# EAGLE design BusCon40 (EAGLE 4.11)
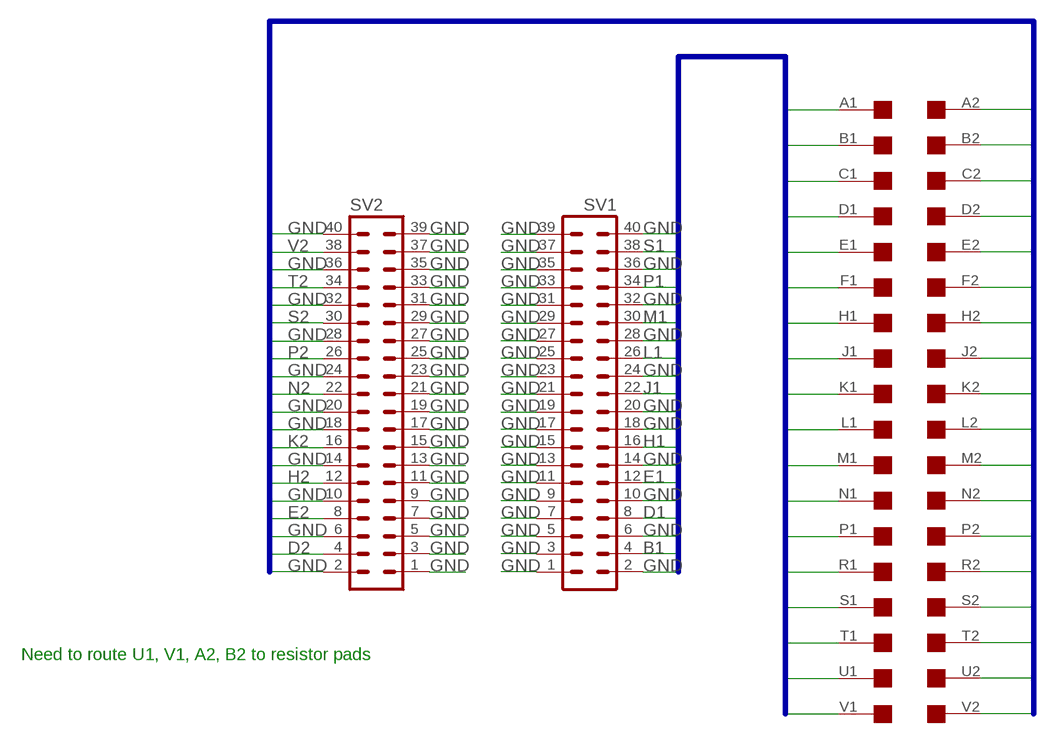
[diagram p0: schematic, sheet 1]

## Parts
SV1  MA20-2W  [MA20-2W]
SV2  MA20-2W  [MA20-2W]
U$1  DEC-FLIPCHIP  [DEC-FLIPCHIP]

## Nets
A2: U$1.A2
B1: SV1.4 U$1.B1
B2: U$1.B2
D1: SV1.8 U$1.D1
D2: SV2.4 U$1.D2
E1: SV1.12 U$1.E1
E2: SV2.8 U$1.E2
GND: SV1.1 SV1.2 SV1.3 SV1.5 SV1.6 SV1.7 SV1.9 SV1.10 SV1.11 SV1.13 SV1.14 SV1.15 SV1.17 SV1.18 SV1.19 SV1.20 SV1.21 SV1.23 SV1.24 SV1.25 SV1.27 SV1.28 SV1.29 SV1.31 SV1.32 SV1.33 SV1.35 SV1.36 SV1.37 SV1.39 SV1.40 SV2.1 SV2.2 SV2.3 SV2.5 SV2.6 SV2.7 SV2.9 SV2.10 SV2.11 SV2.13 SV2.14 SV2.15 SV2.17 SV2.18 SV2.19 SV2.20 SV2.21 SV2.23 SV2.24 SV2.25 SV2.27 SV2.28 SV2.29 SV2.31 SV2.32 SV2.33 SV2.35 SV2.36 SV2.37 SV2.39 SV2.40 U$1.A1 U$1.C1 U$1.C2 U$1.F1 U$1.F2 U$1.J2 U$1.K1 U$1.L2 U$1.M2 U$1.N1 U$1.R1 U$1.R2 U$1.T1 U$1.U2
H1: SV1.16 U$1.H1
H2: SV2.12 U$1.H2
J1: SV1.22 U$1.J1
K2: SV2.16 U$1.K2
L1: SV1.26 U$1.L1
M1: SV1.30 U$1.M1
N2: SV2.22 U$1.N2
P1: SV1.34 U$1.P1
P2: SV2.26 U$1.P2
S1: SV1.38 U$1.S1
S2: SV2.30 U$1.S2
T2: SV2.34 U$1.T2
U1: U$1.U1
V1: U$1.V1
V2: SV2.38 U$1.V2

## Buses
A1,B1,C1,D1,E1,F1,H1,J1,K1,L1,M1,N1,P1,R1,S1,T1,U1,V1
A2,B2,C2,D2,E2,F2,H2,J2,K2,L2,M2,N2,P2,R2,S2,T2,U2,V2

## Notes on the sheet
- Need to route U1, V1, A2, B2 to resistor pads

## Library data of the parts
SV1 SV2 = con-lstb:MA20-2W: PIN HEADER
U$1 = con-dec:DEC-FLIPCHIP: DEC Flip-Chip single card fingers

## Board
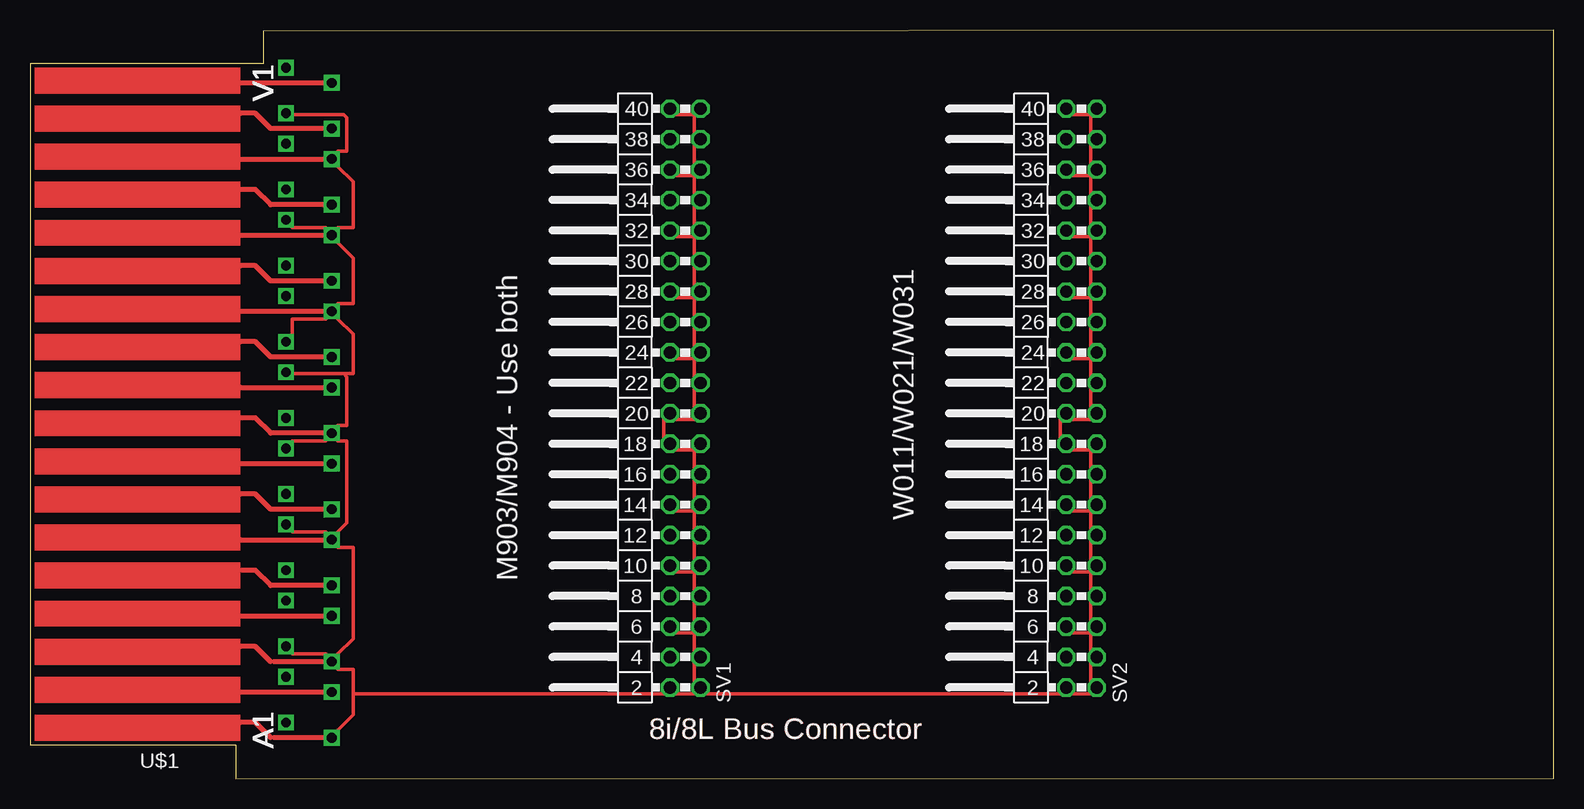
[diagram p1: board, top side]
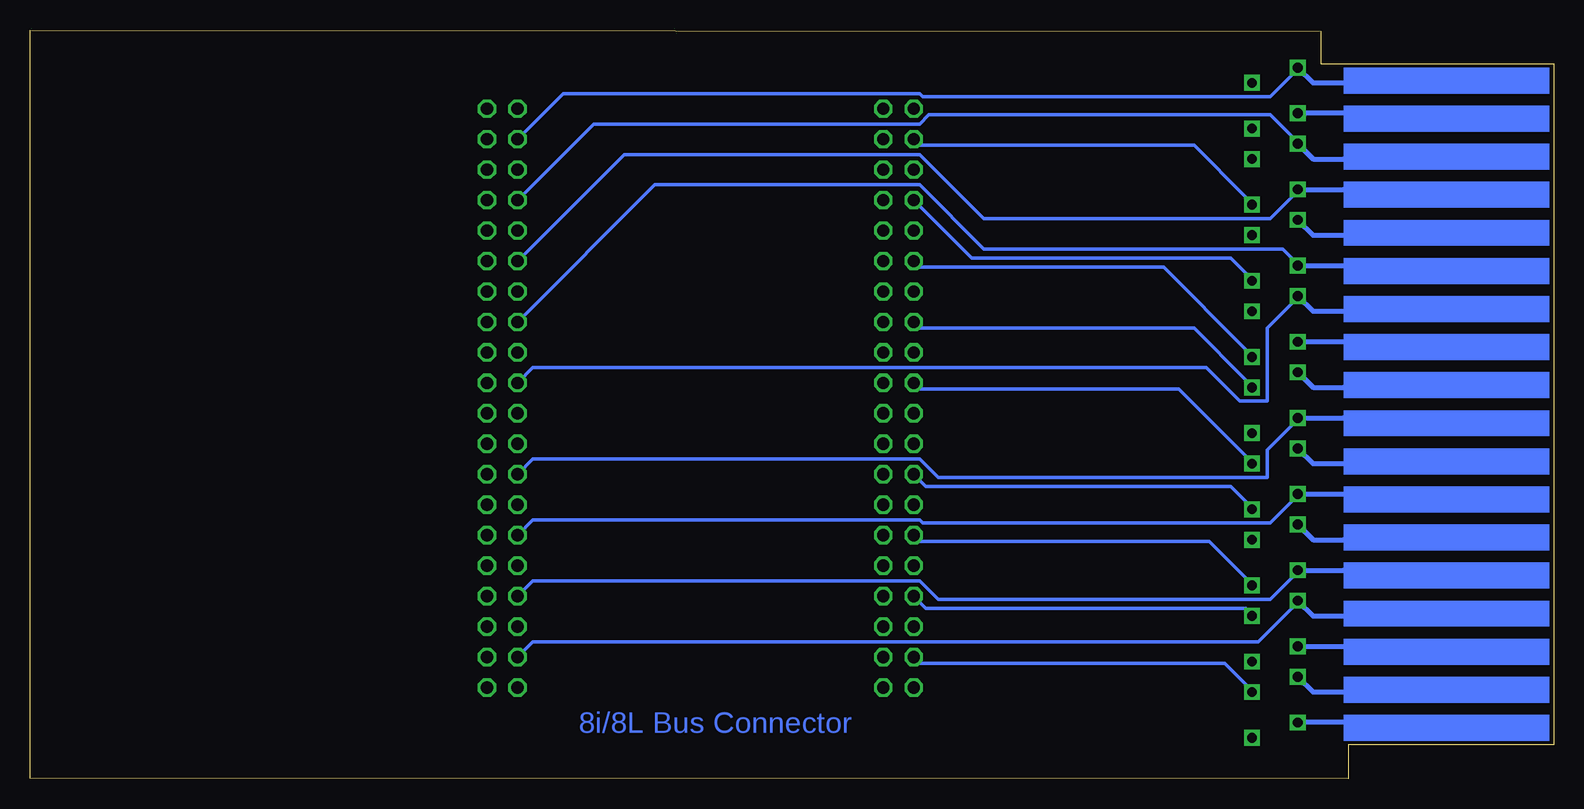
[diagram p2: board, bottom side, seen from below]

Size 126.98 x 62.45 mm. Coordinates in mm from the lower left corner, seen from the top.
Outline: 0,2.83 17.14,2.83 17.14,0 126.98,0.04 126.98,62.45 19.43,62.36 19.43,59.65 0,59.65 0,2.83
Copper layers (1*16): Top 0.035mm / dielectric 1.5mm / Bottom 0.035mm
Design rules "10mils": minimum track width 12mil, minimum drill 28mil, track to track 10mil, track to pad 10mil, pad to pad 10mil, via to via 10mil, smd to smd 10mil, copper to edge 40mil, drill to drill 10mil, minimum pad ring 10mil, minimum via ring 8mil, stop-mask expansion 0mil, vias tented up to drill 0mil, thermal gap 10mil

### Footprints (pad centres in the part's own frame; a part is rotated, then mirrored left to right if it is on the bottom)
MA20-2W = drill 1.016 octagon: 1 -24.13,-1.27; 2 -24.13,1.27; 3 -21.59,-1.27; 4 -21.59,1.27; 5 -19.05,-1.27; 6 -19.05,1.27; 7 -16.51,-1.27; 8 -16.51,1.27; 9 -13.97,-1.27; 10 -13.97,1.27; 11 -11.43,-1.27; 12 -11.43,1.27; 13 -8.89,-1.27; 14 -8.89,1.27; 15 -6.35,-1.27; 16 -6.35,1.27; 17 -3.81,-1.27; 18 -3.81,1.27; 19 -1.27,-1.27; 20 -1.27,1.27; 21 1.27,-1.27; 22 1.27,1.27; 23 3.81,-1.27; 24 3.81,1.27; 25 6.35,-1.27; 26 6.35,1.27; 27 8.89,-1.27; 28 8.89,1.27; 29 11.43,-1.27; 30 11.43,1.27; 31 13.97,-1.27; 32 13.97,1.27; 33 16.51,-1.27; 34 16.51,1.27; 35 19.05,-1.27; 36 19.05,1.27; 37 21.59,-1.27; 38 21.59,1.27; 39 24.13,-1.27; 40 24.13,1.27
DEC-FLIPCHIP = drill 0.813 square: A1 -7.62,27.94; A2 -3.81,26.67; B1 -7.62,24.13; B2 -3.81,22.86; C1 -7.62,21.59; C2 -3.81,20.32; D1 -7.62,17.78; D2 -3.81,16.51; E1 -7.62,15.24; E2 -3.81,13.97; F1 -7.62,11.43; F2 -3.81,10.16; H1 -7.62,8.89; H2 -3.81,7.62; J1 -7.62,5.08; J2 -3.81,3.81; K1 -7.62,2.54; K2 -3.81,1.27; L1 -7.62,-1.27; L2 -3.81,-2.54; M1 -7.62,-3.81; M2 -3.81,-5.08; N1 -7.62,-7.62; N2 -3.81,-8.89; P1 -7.62,-10.16; P2 -3.81,-11.43; R1 -7.62,-13.97; R2 -3.81,-15.24; S1 -7.62,-16.51; S2 -3.81,-17.78; T1 -7.62,-20.32; T2 -3.81,-21.59; U1 -7.62,-22.86; U2 -3.81,-24.13; V1 -7.62,-26.67; V2 -3.81,-27.94

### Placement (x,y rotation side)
SV1  54.6,31.75 90 top
SV2  87.62,31.75 90 top
U$1  17.52,31.37 180 top

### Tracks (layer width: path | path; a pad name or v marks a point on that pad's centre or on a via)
B1
  Bottom 0.305: U$1.B1 25.65,7.87 27.43,9.65 52.83,9.65 SV1.4
D1
  Bottom 0.305: U$1.D1 25.65,14.22 52.32,14.22 SV1.8
D2
  Bottom 0.305: U$1.D2 21.84,14.22 24.63,11.43 85.09,11.43 SV2.4
E1
  Bottom 0.305: U$1.E1 25.65,16.76 28.7,19.81 52.83,19.81 SV1.12
E2
  Bottom 0.305: U$1.E2 21.84,16.76 23.62,14.99 51.3,14.99 52.83,16.51 85.09,16.51 SV2.8
GND
  Top 0.305: 88.39,12.19 86.86,12.19 SV2.6 | 88.39,12.19 88.39,10.67 SV2.3 88.39,9.65 88.39,8.13 SV2.1 88.39,7.11 86.86,7.11 SV2.2 85.85,7.11 56.38,7.11 SV1.1 | 88.39,12.19 SV2.5 88.39,13.21 88.39,14.73 SV2.7 88.39,15.75 88.39,17.27 | 88.39,17.27 86.86,17.27 SV2.10 | 88.39,22.35 86.86,22.35 SV2.14 | 88.39,22.35 88.39,20.83 SV2.11 88.39,19.81 88.39,18.29 SV2.9 88.39,17.27 | 88.39,22.35 SV2.13 88.39,23.37 88.39,24.89 SV2.15 88.39,25.91 88.39,27.43 | 88.39,45.21 86.86,45.21 SV2.32 | 88.39,55.37 86.86,55.37 SV2.40 | 88.39,50.29 86.86,50.29 SV2.36 | 88.39,55.37 88.39,53.85 SV2.37 88.39,52.83 88.39,51.31 SV2.35 88.39,50.29 | 88.39,55.37 SV2.39 | 88.39,50.29 88.39,48.77 SV2.33 88.39,47.75 88.39,46.23 SV2.31 88.39,45.21 | 88.39,27.43 86.86,27.43 SV2.18 85.85,28.45 85.85,29.97 SV2.20 86.86,29.97 88.39,29.97 SV2.19 88.39,30.99 88.39,32.51 SV2.21 88.39,33.53 88.39,35.05 | 88.39,35.05 86.86,35.05 SV2.24 | 88.39,40.13 86.86,40.13 SV2.28 | 88.39,40.13 88.39,38.61 SV2.25 88.39,37.59 88.39,36.07 SV2.23 88.39,35.05 | 88.39,40.13 SV2.27 88.39,41.15 88.39,42.67 SV2.29 88.39,43.69 88.39,45.21 | 88.39,27.43 SV2.17 | SV1.1 55.37,7.11 53.84,7.11 SV1.2 52.83,7.11 26.92,7.11 | SV1.1 55.37,8.13 55.37,9.65 SV1.3 55.37,10.67 55.37,12.19 | 55.37,12.19 53.84,12.19 SV1.6 | 55.37,12.19 SV1.5 55.37,13.21 55.37,14.73 SV1.7 55.37,15.75 55.37,17.27 | 55.37,17.27 53.84,17.27 SV1.10 | 55.37,22.35 53.84,22.35 SV1.14 | 55.37,22.35 55.37,20.83 SV1.11 55.37,19.81 55.37,18.29 SV1.9 55.37,17.27 | 55.37,22.35 SV1.13 55.37,23.37 55.37,24.89 SV1.15 55.37,25.91 55.37,27.43 | 55.37,45.21 53.84,45.21 SV1.32 | 55.37,55.37 53.84,55.37 SV1.40
  Top 0.305: 55.37,50.29 53.84,50.29 SV1.36 | 55.37,55.37 55.37,53.85 SV1.37 55.37,52.83 55.37,51.31 SV1.35 55.37,50.29 | 55.37,55.37 SV1.39 | 55.37,50.29 55.37,48.77 SV1.33 55.37,47.75 55.37,46.23 SV1.31 55.37,45.21 | 55.37,27.43 53.84,27.43 SV1.18 52.83,28.45 52.83,29.97 SV1.20 53.84,29.97 55.37,29.97 SV1.19 55.37,30.99 55.37,32.51 SV1.21 55.37,33.53 55.37,35.05 | 55.37,35.05 53.84,35.05 SV1.24 | 55.37,40.13 53.84,40.13 SV1.28 | 55.37,40.13 55.37,38.61 SV1.25 55.37,37.59 55.37,36.07 SV1.23 55.37,35.05 | 55.37,40.13 SV1.27 55.37,41.15 55.37,42.67 SV1.29 55.37,43.69 55.37,45.21 | 55.37,27.43 SV1.17 | U$1.R2 21.84,45.97 24.63,45.97 U$1.R1 | U$1.R1 25.65,45.97 26.92,45.97 26.92,49.78 25.65,51.05 U$1.T1 25.65,52.32 26.41,52.32 26.41,55.12 26.16,55.37 21.84,55.37 U$1.U2 | U$1.C2 21.84,10.41 24.63,10.41 U$1.C1 | 26.92,7.11 26.92,9.14 25.65,9.14 U$1.C1 | 26.92,7.11 26.92,5.33 25.65,4.06 U$1.A1 | U$1.M2 21.84,37.08 21.84,38.35 24.63,38.35 U$1.N1 | U$1.F2 21.84,20.57 24.63,20.57 U$1.F1 | U$1.J2 21.84,28.19 24.63,28.19 U$1.K1 | 26.16,33.78 21.84,33.78 U$1.L2 | 26.16,33.78 26.41,33.53 26.41,29.46 25.65,29.46 U$1.K1 | U$1.F1 25.65,20.57 26.41,21.34 26.41,28.19 25.65,28.19 U$1.K1 | 26.16,33.78 26.92,33.78 26.92,37.08 25.65,38.35 U$1.N1 | U$1.C1 25.65,10.41 26.92,11.68 26.92,19.3 25.65,19.3 U$1.F1 | U$1.R1 25.65,44.7 26.92,43.43 26.92,39.62 25.65,39.62 U$1.N1
H1
  Bottom 0.305: U$1.H1 25.65,23.11 26.92,24.38 52.32,24.38 SV1.16
H2
  Bottom 0.305: U$1.H2 21.84,23.11 23.62,21.34 52.57,21.34 52.83,21.59 85.09,21.59 SV2.12
J1
  Bottom 0.305: U$1.J1 25.65,26.92 31.24,32.51 52.83,32.51 SV1.22
K2
  Bottom 0.305: U$1.K2 21.84,29.46 23.87,27.43 23.87,25.15 51.3,25.15 52.83,26.67 85.09,26.67 SV2.16
L1
  Bottom 0.305: U$1.L1 25.65,33.27 29.97,37.59 52.83,37.59 SV1.26
M1
  Bottom 0.305: U$1.M1 25.65,35.81 32.51,42.67 52.83,42.67 SV1.30
N2
  Bottom 0.305: U$1.N2 21.84,39.62 23.87,37.59 23.87,31.5 26.16,31.5 28.95,34.29 85.09,34.29 SV2.22
P1
  Bottom 0.305: U$1.P1 25.65,42.16 26.92,43.43 48.51,43.43 SV1.34
P2
  Bottom 0.305: U$1.P2 21.84,43.43 22.6,44.2 47.49,44.2 52.83,49.53 74.93,49.53 SV2.26
S1
  Bottom 0.305: U$1.S1 25.65,48.51 29.97,52.83 52.83,52.83 SV1.38
S2
  Bottom 0.305: U$1.S2 21.84,48.51 23.62,46.74 47.49,46.74 52.83,52.07 77.47,52.07 SV2.30
T2
  Bottom 0.305: U$1.T2 21.84,53.59 23.62,55.37 52.06,55.37 52.83,54.61 80.01,54.61 SV2.34
V2
  Bottom 0.305: U$1.V2 21.84,58.67 23.62,56.9 52.57,56.9 52.83,57.15 82.55,57.15 SV2.38

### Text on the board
Top: 8i/8L Bus Connector
Bottom: 8i/8L Bus Connector
tPlace: W011/W021/W031 | M903/M904 - Use both | 8i/8L Bus Connector
tNames: V1 | V1 | V1 | V1 | V1 | V1 | V1 | V1 | V1 | V1 | V1 | V1 | V1 | V1 | V1 | V1 | V1 | V1 | V1 | V1 | V1 | V1 | V1 | V1 | V1 | V1 | V1 | V1 | V1 | V1 | V1 | V1 | A1 | A1 | A1 | A1 | A1 | A1 | A1 | A1 | A1 | A1 | A1 | A1 | A1 | A1 | A1 | A1 | A1 | A1 | A1 | A1 | A1 | A1 | A1 | A1 | A1 | A1 | A1 | A1 | A1 | A1 | A1 | A1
